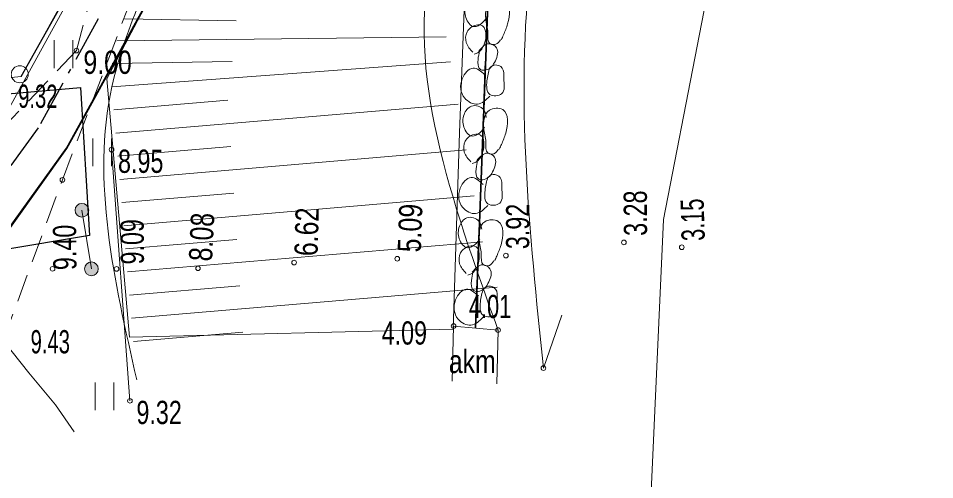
# Model space of a CAD drawing. Extents: x 514052 to 514314, y 297701 to 297876.
# Drawn here: x 514231.91 to 514251.62, y 297762.66 to 297772.58 of the extents above; entities that cross this region are included whole.
import ezdxf

# ---------------------------------------------------------------- set-up
doc = ezdxf.new("R2010")
doc.units = 0
doc.header["$LTSCALE"] = 0.2
doc.linetypes.add('DOT_DASHED', pattern=[7.7, 5, -1.2, 0.3, -1.2])
doc.linetypes.add('MEDIUM_DASHED', pattern=[4.5, 3, -1.5])
for name, color, linetype, lineweight in [('1', 7, 'Continuous', 13), ('16', 7, 'Continuous', 13), ('17', 7, 'Continuous', 13), ('18', 7, 'Continuous', 13), ('19', 7, 'Continuous', 25), ('21', 7, 'Continuous', 13), ('35', 7, 'Continuous', 25), ('5', 7, 'Continuous', 13), ('55', 7, 'Continuous', 13), ('56', 7, 'Continuous', 13), ('6', 7, 'Continuous', 13), ('61', 7, 'Continuous', 13), ('62', 7, 'Continuous', 13), ('63', 7, 'Continuous', 13), ('7', 7, 'Continuous', 13)]:
    doc.layers.add(name, color=color, linetype=linetype, lineweight=lineweight)
doc.layers.add('15', color=7, linetype='Continuous')
doc.layers.add('8', color=7, linetype='Continuous')

msp = doc.modelspace()

# ---------------------------------------------------------------- hatches: boundary and pattern name
at = {"layer": '7'}
for points in [[(514233.4242, 297768.4531, 1), (514233.1277, 297768.4531, 1)], [(514233.6282, 297767.1921, 1), (514233.3317, 297767.1921, 1)]]:
    msp.add_hatch(color=256, dxfattribs=at).paths.add_polyline_path(points)

# ---------------------------------------------------------------- linework, layer by layer
at = {"layer": '1'}
for p, q in [((514234.192, 297772.571), (514236.597, 297772.527)), ((514234.029, 297772.099), (514241.113, 297772.188)), ((514233.92, 297771.11), (514241.208, 297771.65)), ((514233.93, 297771.609), (514236.505, 297771.651)), ((514233.962, 297770.612), (514236.413, 297770.82)), ((514234.005, 297770.114), (514241.369, 297770.739)), ((514234.047, 297769.616), (514236.478, 297769.822)), ((514234.089, 297769.118), (514241.544, 297769.751)), ((514234.132, 297768.619), (514236.542, 297768.824)), ((514234.174, 297768.121), (514241.718, 297768.762)), ((514234.216, 297767.623), (514236.607, 297767.826)), ((514234.259, 297767.125), (514241.893, 297767.773)), ((514234.301, 297766.626), (514236.672, 297766.828)), ((514234.343, 297766.128), (514242.212, 297766.797)), ((514234.386, 297765.63), (514236.736, 297765.83)), ((514234.428, 297765.132), (514234.429, 297765.132))]:
    msp.add_line(p, q, dxfattribs=at)
msp.add_circle((514231.9377, 297771.3791), 0.1827, dxfattribs=at)
msp.add_spline([(514260.862, 297805.466), (514258.749, 297804.839), (514257.459, 297803.011), (514254.953, 297800.933), (514250.105, 297795.245), (514240.136, 297784.718), (514236.07, 297778.812), (514235.246, 297774.955), (514233.92, 297771.109), (514234.456, 297764.804)], degree=3, dxfattribs=at)
at = {"layer": '16'}
msp.add_line((514233.48, 297767.192), (514233.276, 297768.453), dxfattribs=at)
at = {"layer": '17'}
msp.add_line((514233.913, 297769.758), (514234.309, 297764.353), dxfattribs=at)
at = {"layer": '18'}
msp.add_lwpolyline([(514233.11, 297763.683), (514232.706, 297764.266), (514232.13, 297764.952), (514231.583, 297765.652), (514230.737, 297766.24), (514229.941, 297766.887), (514229.112, 297767.498), (514228.248, 297768.049), (514227.353, 297768.518), (514226.427, 297768.883), (514225.472, 297769.121), (514223.532, 297769.217)], dxfattribs=at)
at = {"layer": '19', "lineweight": 13}
msp.add_spline([(514243.205, 297765.058), (514242.936, 297773.769), (514245.025, 297781.038), (514246.54, 297783.925), (514249.054, 297787.013), (514257.225, 297795.21), (514260.154, 297798.886), (514267.863, 297801.516), (514273.305, 297805.826), (514276.583, 297807.615)], degree=3, dxfattribs=at)
at = {"layer": '21'}
msp.add_line((514243.205, 297765.058), (514243.601, 297766.197), dxfattribs=at)
at = {"layer": '35'}
msp.add_lwpolyline([(514231.97, 297771.331), (514233.541, 297774.128), (514233.667, 297780.485), (514240.255, 297787.177), (514246.843, 297793.868), (514250.774, 297798.68), (514254.387, 297803.352), (514256.058, 297805.511), (514258.694, 297808.915), (514260.151, 297809.248), (514268.632, 297811.186)], dxfattribs=at)
at = {"layer": '35', "lineweight": 35}
msp.add_lwpolyline([(514271.3, 297810.152), (514259.606, 297807.499), (514252.681, 297798.474), (514245.829, 297790.57), (514238.515, 297783.139), (514236.323, 297779.764), (514235.19, 297775.821), (514235.133, 297773.758), (514233.372, 297770.559)], dxfattribs=at)
at = {"layer": '5'}
for p, q in [((514232.68, 297771.513), (514232.68, 297772.113)), ((514233.08, 297771.513), (514233.08, 297772.113)), ((514233.51, 297769.399), (514233.51, 297769.999)), ((514233.91, 297769.399), (514233.91, 297769.999)), ((514233.564, 297764.15), (514233.564, 297764.75)), ((514233.964, 297764.15), (514233.964, 297764.75))]:
    msp.add_line(p, q, dxfattribs=at)
at = {"layer": '55'}
for points in [[(514217.339, 297769.84), (514231.97, 297771.331), (514233.541, 297774.128), (514233.602, 297778.964), (514248.877, 297796.499), (514258.817, 297808.985), (514270.863, 297811.577), (514272.894, 297813.849)], [(514245.484, 297761.608), (514245.786, 297768.251), (514247.238, 297775.723), (514250.297, 297781.961), (514257.654, 297790.318), (514259.345, 297792.1), (514261.879, 297793.446), (514269.393, 297799.625), (514276.431, 297803.309), (514278.49, 297803.954), (514281.804, 297808.459), (514282.968, 297810.375)]]:
    msp.add_lwpolyline(points, dxfattribs=at)
at = {"layer": '56'}
msp.add_line((514241.273, 297765.961), (514241.241, 297764.776), dxfattribs=at)
msp.add_lwpolyline([(514241.273, 297765.961), (514242.228, 297765.875), (514242.203, 297764.715)], dxfattribs=at)
at = {"layer": '6'}
for centre in [(514233.159, 297771.8881), (514233.913, 297769.7582), (514232.855, 297769.1072), (514244.9366, 297767.7622), (514246.1816, 297767.6562), (514240.061, 297767.4111), (514242.398, 297767.4781), (514232.6439, 297767.1932), (514235.773, 297767.2042), (514237.8399, 297767.3271), (514234.022, 297767.1901), (514241.273, 297765.9611), (514242.2279, 297765.8751), (514243.2049, 297765.0581), (514234.3089, 297764.3531)]:
    msp.add_circle(centre, 0.05, dxfattribs=at)
at = {"layer": '61'}
msp.add_lwpolyline([(514219.342, 297770.059), (514231.967, 297771.335), (514233.539, 297774.175), (514233.667, 297780.485), (514246.843, 297793.868)], dxfattribs=at)
at = {"layer": '62'}
msp.add_spline([(514242.228, 297765.875), (514240.809, 297773.912), (514243.289, 297779.448), (514244.466, 297781.572), (514244.559, 297781.63), (514245.987, 297783.723), (514248.871, 297787.176), (514251.243, 297789.878), (514252.476, 297791.159), (514253.723, 297792.429), (514256.513, 297795.415), (514260.533, 297799.834), (514263.587, 297801.907), (514261.268, 297805.481)], degree=3, dxfattribs=at)
at = {"layer": '63', "linetype": 'MEDIUM_DASHED'}
for points in [[(514231.583, 297765.652), (514232.855, 297769.107), (514235.126, 297775.062), (514235.802, 297779.27), (514240.035, 297784.801), (514250.098, 297795.488), (514254.893, 297801.043), (514257.448, 297803.118), (514259.485, 297807.223), (514261.814, 297808.455), (514265.145, 297808.86), (514272.105, 297811.112)], [(514249.225, 297796.455), (514239.453, 297785.495), (514234.344, 297779.635), (514234.008, 297775.04), (514233.159, 297771.888), (514231.647, 297770.296), (514228.019, 297768.169)]]:
    msp.add_lwpolyline(points, dxfattribs=at)
at = {"layer": '63', "linetype": 'DOT_DASHED', "lineweight": 25}
for points in [[(514271.134, 297810.883), (514259.176, 297808.17), (514252.1, 297798.948), (514245.278, 297791.079), (514237.927, 297783.611), (514235.633, 297780.079), (514234.443, 297775.937), (514234.388, 297773.96), (514232.332, 297770.225), (514229.92, 297766.887)], [(514241.744, 297765.925), (514242.057, 297774.207), (514242.797, 297776.707), (514244.225, 297779.218), (514245.964, 297781.323), (514250.712, 297786.706), (514257.523, 297794.362), (514261.299, 297799.094), (514264.423, 297802.109), (514265.043, 297802.596), (514265.222, 297802.656), (514267.352, 297803.342), (514273.537, 297806.201)]]:
    msp.add_lwpolyline(points, dxfattribs=at)
at = {"layer": '63', "lineweight": 35}
for points in [[(514241.744, 297765.925), (514242.057, 297774.207), (514242.797, 297776.707), (514244.225, 297779.218), (514245.094, 297780.271), (514245.964, 297781.323), (514248.338, 297784.015), (514250.712, 297786.706), (514254.118, 297790.534), (514257.523, 297794.362), (514259.411, 297796.728), (514261.299, 297799.094), (514262.861, 297800.601), (514264.423, 297802.109), (514265.043, 297802.596), (514267.352, 297803.342), (514273.537, 297806.201)], [(514233.372, 297770.559), (514232.941, 297769.78), (514230.547, 297766.433)]]:
    msp.add_lwpolyline(points, dxfattribs=at)
at = {"layer": '63'}
for points in [[(514249.255, 297794.522), (514245.829, 297790.57), (514241.829, 297786.505), (514238.515, 297783.139), (514236.314, 297779.769), (514235.179, 297775.815), (514235.126, 297773.769), (514232.94, 297769.786), (514230.528, 297766.448), (514229.312, 297767.326), (514231.675, 297770.587), (514233.643, 297774.162), (514233.696, 297776.053), (514234.943, 297780.394), (514237.339, 297784.083), (514241.033, 297787.835), (514244.727, 297791.588)], [(514241.56, 297774.289), (514241.402, 297770.117), (514241.26, 297765.893), (514234.297, 297765.719), (514233.812, 297771.282), (514235.126, 297773.769)]]:
    msp.add_lwpolyline(points, dxfattribs=at)
at = {"layer": '63', "lineweight": 25}
msp.add_lwpolyline([(514226.481, 297770.509), (514233.246, 297771.097), (514233.442, 297767.909), (514229.618, 297767.271)], close=True, dxfattribs=at)
at = {"layer": '63', "lineweight": 35}
msp.add_spline([(514215.228, 297765.323), (514215.206, 297772.763), (514216.383, 297781.396), (514219.324, 297786.104), (514225.403, 297788.655), (514229.52, 297789.636), (514235.599, 297788.066)], degree=3, dxfattribs=at)
at = {"layer": '63'}
for points in [[(514242.017, 297772.807), (514241.961, 297772.973), (514241.7, 297773.049), (514241.54, 297772.866), (514241.535, 297772.599), (514241.715, 297772.404), (514241.883, 297772.479), (514241.982, 297772.596)], [(514242.281, 297772.124), (514242.182, 297772.025), (514242.059, 297772.036), (514242.008, 297772.272), (514241.962, 297772.58), (514242.085, 297772.962), (514242.371, 297772.973), (514242.435, 297772.468), (514242.344, 297772.226), (514242.299, 297772.122)], [(514241.686, 297771.853), (514241.544, 297772.062), (514241.563, 297772.293), (514241.755, 297772.437), (514241.896, 297772.425), (514241.966, 297772.204), (514241.932, 297772.028), (514241.793, 297771.844), (514241.717, 297771.815)], [(514241.812, 297771.878), (514242.041, 297772.037), (514242.194, 297771.952), (514242.17, 297771.669), (514241.974, 297771.472), (514241.851, 297771.483), (514241.798, 297771.701), (514241.83, 297771.876)], [(514242.049, 297771.518), (514241.99, 297771.237), (514242.054, 297770.945), (514242.306, 297770.96), (514242.352, 297771.295), (514242.317, 297771.514), (514242.162, 297771.58), (514242.049, 297771.518)], [(514241.947, 297771.366), (514241.692, 297771.513), (514241.458, 297771.283), (514241.511, 297770.868), (514241.787, 297770.737), (514242.052, 297770.911)], [(514241.975, 297770.452), (514241.919, 297770.618), (514241.658, 297770.694), (514241.498, 297770.511), (514241.493, 297770.244), (514241.673, 297770.049), (514241.841, 297770.124), (514241.939, 297770.241)], [(514242.239, 297769.769), (514242.14, 297769.67), (514242.017, 297769.681), (514241.966, 297769.917), (514241.92, 297770.225), (514242.042, 297770.607), (514242.329, 297770.618), (514242.393, 297770.113), (514242.302, 297769.871), (514242.257, 297769.767)], [(514241.644, 297769.497), (514241.502, 297769.707), (514241.521, 297769.938), (514241.712, 297770.082), (514241.854, 297770.069), (514241.924, 297769.849), (514241.89, 297769.673), (514241.751, 297769.488), (514241.675, 297769.46)], [(514241.77, 297769.523), (514241.999, 297769.682), (514242.152, 297769.597), (514242.128, 297769.314), (514241.932, 297769.117), (514241.809, 297769.127), (514241.756, 297769.345), (514241.788, 297769.521)], [(514242.007, 297769.163), (514241.948, 297768.882), (514242.012, 297768.59), (514242.264, 297768.605), (514242.31, 297768.94), (514242.275, 297769.158), (514242.12, 297769.224), (514242.007, 297769.163)], [(514241.905, 297769.011), (514241.65, 297769.158), (514241.416, 297768.928), (514241.469, 297768.513), (514241.745, 297768.382), (514242.01, 297768.556)], [(514241.876, 297768.05), (514241.819, 297768.215), (514241.558, 297768.291), (514241.399, 297768.108), (514241.394, 297767.841), (514241.574, 297767.647), (514241.74, 297767.722), (514241.84, 297767.839)], [(514242.138, 297767.366), (514242.041, 297767.268), (514241.917, 297767.278), (514241.866, 297767.514), (514241.821, 297767.822), (514241.943, 297768.205), (514242.23, 297768.215), (514242.294, 297767.71), (514242.201, 297767.469), (514242.156, 297767.365)], [(514241.544, 297767.095), (514241.401, 297767.304), (514241.422, 297767.536), (514241.612, 297767.679), (514241.755, 297767.667), (514241.825, 297767.446), (514241.791, 297767.271), (514241.651, 297767.086), (514241.576, 297767.058)], [(514241.671, 297767.12), (514241.9, 297767.28), (514242.053, 297767.195), (514242.028, 297766.911), (514241.833, 297766.714), (514241.709, 297766.725), (514241.655, 297766.943), (514241.689, 297767.119)], [(514241.806, 297766.609), (514241.55, 297766.756), (514241.316, 297766.526), (514241.37, 297766.111), (514241.645, 297765.98), (514241.91, 297766.154)], [(514241.908, 297766.761), (514241.849, 297766.48), (514241.913, 297766.188), (514242.165, 297766.203), (514242.211, 297766.538), (514242.176, 297766.756), (514242.021, 297766.822), (514241.908, 297766.761)]]:
    msp.add_spline(points, degree=3, dxfattribs=at)
at = {"layer": '7'}
for centre in [(514233.2759, 297768.4531), (514233.48, 297767.1921)]:
    msp.add_circle(centre, 0.1483, dxfattribs=at)

# ---------------------------------------------------------------- texts
at = {"layer": '15', "width": 0.8}
msp.add_text('akm', height=0.5, dxfattribs=at).set_placement((514241.169, 297764.95))
at = {"layer": '8'}
for s, width, p in [(' 9.00', 0.8, (514233.159, 297771.388)), ('9.32', 0.65, (514231.904, 297770.657)), (' 8.95', 0.75, (514233.913, 297769.258)), (' 4.01', 0.7, (514241.471, 297766.133)), (' 4.09', 0.75, (514239.585, 297765.563)), ('9.43', 0.65, (514232.172, 297765.374)), (' 9.32', 0.75, (514234.309, 297763.853))]:
    msp.add_text(s, height=0.5, dxfattribs=dict(at, width=width)).set_placement(p)
for s, rotation, width, p in [(' 3.28', 90.362, 0.75, (514245.437, 297767.765)), (' 3.15', 91.617, 0.7, (514246.681, 297767.67)), (' 6.62', 88.376, 0.8, (514238.34, 297767.313)), (' 5.09', 87.969, 0.8, (514240.561, 297767.393)), (' 3.92', 89.822, 0.75, (514242.898, 297767.477)), (' 9.09', 90.364, 0.75, (514234.611, 297767.149)), (' 8.08', 87.23, 0.8, (514236.067, 297767.198)), (' 9.40', 90.596, 0.75, (514233.162, 297767.029))]:
    msp.add_text(s, height=0.5, rotation=rotation, dxfattribs=dict(at, width=width)).set_placement(p)

doc.saveas('drawing.dxf')
